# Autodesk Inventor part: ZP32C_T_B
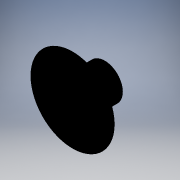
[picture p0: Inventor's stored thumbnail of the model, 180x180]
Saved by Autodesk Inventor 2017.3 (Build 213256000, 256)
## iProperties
Part Number: ZP32C_T_B
Material: Generic
Catalog Web Link: www.cadenas.de
Description: ZPT_20_32_B_PAD-Vacuum Pad/Vertical Vacuum Entry With Buffer
Vendor: SMC
Document SubType Name: Modeling
Designer: partserver
Manufacturer: SMC
Mass: 2.66352 g
Surface Area: 26.1589 cm^2
Volume: 2.66352 cm^3
Density: 1 g/cm^3
Appearance: PSOLRGB-0-0-0
Category: PARTsolutions
Company: SMC
Title: ZP32C
Author: Cadenas PARTsolutions
Comments: Vacuum Pad/Vertical Vacuum Entry With Buffer
PSOL_IDENT_0: {$CADENAS_DATA\23d-libs\smc_jp\vacuum_equipment\vacuum_pad\zp\zpt_b\zpt_20_32_b\parts\zpt_20_32_pad_
PSOL_IDENT_1: b.prj},164 {VTYP=3D},{NB=ZP32C_T_B},{LINA=ZP32C},{NN=ZPT_20_32_B_PAD},{DATE=03.02.2021 04:23:35},{GE
PSOL_IDENT_2: OMDATE=30.10.2020 07:51:57},{VERSION=},{LINEID=110},{WBVAR=},{WBNUMERIC=}  {NB=ZP32C_T_B},{LINA=ZP32
PSOL_IDENT_3: C},{KT=DUMMY},{DIAMETER=32},{PAD=(C) Flat with ribs},{PADX=C},{ORDER=ZP32C},{B=35.0},{C=14.5},{M=0.0
PSOL_IDENT_4: },{LV1=10.00},{LV2=5.05},{RX1=8.30},{RY1=6.70},{RX2=19.18},{RY2=59.62},{LV3=0.00},{LV4=0.00},{LV5=0.
PSOL_IDENT_5: 00},{DEG1=0.00},{DEG2=0.00},{DEG3=0.00},{NO=1.000},{A=32},{Y=2.3}
NB: ZP32C_T_B
NN: ZPT_20_32_B_PAD
NT: Vacuum Pad/Vertical Vacuum Entry With Buffer
NBSYN: $ORDER._T_B
LINA: ZP32C
CATALOG: SMC (JP
DIAMETER: 32
PAD: (C) Flat with ribs
B: 35
C: 14.5
M: 0
LV1: 10
LV2: 5.05
RX1: 8.3
RY1: 6.7
RX2: 19.18
RY2: 59.62
LV3: 0
LV4: 0
LV5: 0
DEG1: 0
DEG2: 0
DEG3: 0
NO: 1
A: 32
Y: 2.3
SUPPLIER: SMC
ARTICLENO: ZP32C_T_B
BOMINFO: ZP32C
CREATOR: CADENAS GmbH
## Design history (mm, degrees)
sketch "Sketch_2"
  geometry: L1 (0, 0)-(0, 14.5); L2 (2, 2.3)-(11.068, 2.3); L3 (11.068, 2.3)-(16, 0); L4 (16, 0)-(17.5, 0); L5 (6.5, 6.713)-(6.5, 10); L6 (6.5, 10)-(7.5, 10.577); L7 (7.5, 10.577)-(7.5, 13.423); L8 (7.5, 13.423)-(6.5, 14); L9 (6.5, 14)-(5, 14); L10 (5, 14)-(4.5, 14.5); L11 (4.5, 14.5)-(2, 14.5); L12 (2, 14.5)-(2, 2.3); A1 r 70 centre (-19.18, -59.62) between (17.5, 0) and (7.611, 5.05); A2 r 1.8 centre (8.3, 6.713) between (6.5, 6.713) and (7.611, 5.05)
  constraints: 24 end point, 4 point on circle, 2 centre point
revolve "Revolution1" sketch "Sketch_2" stored, may be unused: angle "d0" = 360 deg
node "adapter_XY"
node "adapter_YZ"
node "adapter_ZX"
node "adapter_X"
node "adapter_Y"
node "adapter_Z"
node "adapter_Center"
node "dummy_XY"
node "dummy_YZ"
node "dummy_ZX"
node "dummy_X"
node "dummy_Y"
node "dummy_Z"
node "dummy_Center"
body "Solid1"
other parameters: "d1" = 0, "d2" = 0
